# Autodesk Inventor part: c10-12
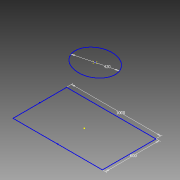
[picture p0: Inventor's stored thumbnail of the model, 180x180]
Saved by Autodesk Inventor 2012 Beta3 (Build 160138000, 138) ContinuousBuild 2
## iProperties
Created: 2011-01
Part Number: c10-12
Material: Aluminum-6061
Document SubType Name: Sheet Metal
Designer: Beta-8540w
Density: 2.71 g/cm^3
Sheet Metal Rule: Aluminum 3 mm
Author: Beta-8540w
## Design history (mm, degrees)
sketch "Sketch1"
  geometry: L1 (-500, -300)-(500, -300); L2 (500, -300)-(500, 300); L3 (500, 300)-(-500, 300); L4 (-500, 300)-(-500, -300); 3 further points
  constraints: 8 end point, 2 midpoint, 2 parallel, 1 horizontal, 1 horizontal alignment, 1 perpendicular, 1 vertical alignment
  dimensions: "d0" = 1000 distance of L3.end L2.end; "d1" = 600 distance of L2.end L1.end
sketch "Sketch2"
  geometry: C1 r 210 at (0, 0); 1 further point
  constraints: 1 centre point, 1 coincident
  dimensions: "d10" = 420 diameter of C1
other parameters: "Thickness" = 3 (derived), "BendRadius" = 2 (derived), "BendReliefWidth" = 3 (= Thickness), "BendReliefDepth" = 1.5 (= 0.5 x Thickness), "CornerReliefSize" = 12 (= 4 x Thickness), "SeamGap" = 0.01, "MinimumRemnant" = 6 (= 2 x Thickness), "TransitionRadius" = 2 (= BendRadius), "JacobiRadiusSize" = 2 (= BendRadius), "GapSize" = 1.5 (= 0.5 x Thickness), "d7" = 5 deg, "d8" = -5 deg, "d9" = 0
